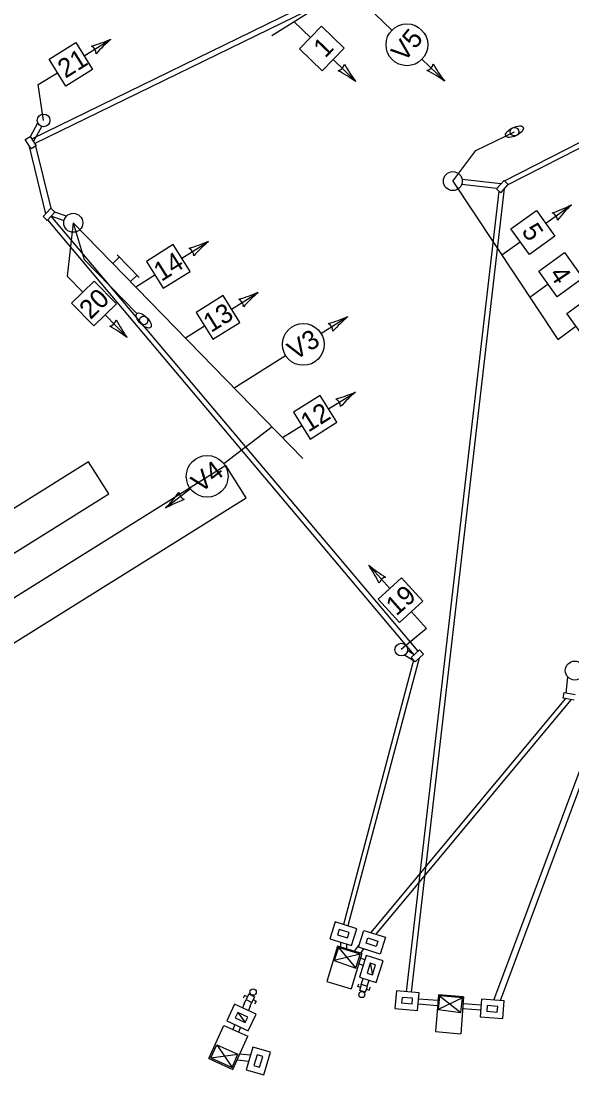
# Model space of a CAD drawing. Extents: x 981632 to 1295361, y 220574 to 1844132.
# Drawn here: x 984464.9 to 984552, y 1843245.1 to 1843411.6 of the extents above; entities that cross this region are included whole.
import ezdxf

# ---------------------------------------------------------------- set-up
doc = ezdxf.new("R2010")
doc.units = 0
for name, color, linetype in [('5', 7, 'Continuous'), ('R_Existing Luminaire', 7, 'Continuous'), ('R_Existing Signal', 7, 'Continuous'), ('R_Existing Signal Heads', 7, 'Continuous'), ('R_Existing Signal Mast Arm', 7, 'Continuous'), ('V-SIGNAL-CONDUIT', 7, 'Continuous'), ('V-SIGNAL-CONTROLLER', 7, 'Continuous'), ('V-SIGNAL-HEAD', 7, 'Continuous'), ('V-SIGNAL-MAST', 7, 'Continuous')]:
    doc.layers.add(name, color=color, linetype=linetype)

msp = doc.modelspace()

# ---------------------------------------------------------------- linework, layer by layer
at = {"layer": '5'}
for p, q in [((984548.62, 1843436.87), (984504.52, 1843409.32)), ((984473.16, 1843379.77), (984509.46, 1843342.53))]:
    msp.add_line(p, q, dxfattribs=at)
at = {"layer": 'R_Existing Luminaire'}
for p, q in [((984536.76, 1843391.22), (984542.88, 1843394.16)), ((984533.14, 1843386.36), (984536.76, 1843391.22))]:
    msp.add_line(p, q, dxfattribs=at)
msp.add_circle((984542.88, 1843394.17), 0.679, dxfattribs=at)
msp.add_ellipse((984542.88, 1843394.17), major_axis=(1.39, 0.67), ratio=0.441176, dxfattribs=at)
at = {"layer": 'R_Existing Signal'}
for p, q in [((984541.29, 1843386.39), (984590.61, 1843411.62)), ((984541.9, 1843385.8), (984591.25, 1843411.05)), ((984540.75, 1843385.92), (984534.62, 1843386.61)), ((984541.24, 1843386.43), (984540.04, 1843385.16)), ((984541.9, 1843385.8), (984541.24, 1843386.43)), ((984525.82, 1843258.27), (984540.47, 1843384.75)), ((984526.61, 1843258.2), (984541.33, 1843385.2)), ((984540.06, 1843385.19), (984534.54, 1843385.82)), ((984540.04, 1843385.16), (984540.7, 1843384.53)), ((984540.7, 1843384.53), (984541.9, 1843385.8)), ((984539.64, 1843256.94), (984571.61, 1843342.55)), ((984540.69, 1843256.86), (984572.24, 1843341.88)), ((984524.24, 1843258.4), (984524, 1843255.62)), ((984527.81, 1843258.1), (984524.24, 1843258.4)), ((984527.58, 1843255.32), (984527.81, 1843258.1)), ((984525.11, 1843257.37), (984525.04, 1843256.49)), ((984525.04, 1843256.49), (984526.71, 1843256.35)), ((984526.78, 1843257.23), (984525.11, 1843257.37)), ((984526.71, 1843256.35), (984526.78, 1843257.23)), ((984530.72, 1843256.06), (984527.66, 1843256.3)), ((984530.78, 1843256.86), (984527.73, 1843257.1)), ((984530.86, 1843257.8), (984530.39, 1843251.98)), ((984531.03, 1843257.6), (984530.84, 1843255.47)), ((984534.65, 1843257.31), (984530.84, 1843255.47)), ((984534.85, 1843257.48), (984530.86, 1843257.8)), ((984534.65, 1843257.31), (984531.03, 1843257.6)), ((984531.03, 1843257.6), (984534.43, 1843255)), ((984534.85, 1843257.48), (984534.39, 1843251.64)), ((984534.43, 1843255), (984534.65, 1843257.31)), ((984537.61, 1843256.12), (984534.76, 1843256.35)), ((984537.69, 1843257.11), (984537.46, 1843254.32)), ((984541.27, 1843256.81), (984537.69, 1843257.11)), ((984541.04, 1843254.03), (984541.27, 1843256.81)), ((984524, 1843255.62), (984527.58, 1843255.32)), ((984530.84, 1843255.47), (984534.43, 1843255)), ((984537.55, 1843255.33), (984534.7, 1843255.55)), ((984538.57, 1843256.07), (984538.5, 1843255.2)), ((984538.5, 1843255.2), (984540.16, 1843255.06)), ((984540.24, 1843255.93), (984538.57, 1843256.07)), ((984540.16, 1843255.06), (984540.24, 1843255.93)), ((984537.46, 1843254.32), (984541.04, 1843254.03)), ((984530.39, 1843251.98), (984534.39, 1843251.64))]:
    msp.add_line(p, q, dxfattribs=at)
msp.add_circle((984533.14, 1843386.36), 1.5, dxfattribs=at)
at = {"layer": 'R_Existing Signal Heads'}
for p, q in [((984547.82, 1843379.71), (984551.87, 1843382.63)), ((984540.87, 1843374.7), (984543.76, 1843376.78)), ((984545.29, 1843368.02), (984548.18, 1843370.11)), ((984549.71, 1843361.35), (984552.6, 1843363.43))]:
    msp.add_line(p, q, dxfattribs=at)
for points in [[(984545.23, 1843374.76), (984542.3, 1843378.81), (984546.36, 1843381.73), (984549.28, 1843377.68)], [(984549.65, 1843368.08), (984546.72, 1843372.14), (984550.78, 1843375.06), (984553.7, 1843371)], [(984554.07, 1843361.41), (984551.14, 1843365.46), (984555.2, 1843368.38), (984558.13, 1843364.33)]]:
    msp.add_lwpolyline(points, close=True, dxfattribs=at)
for centre, radius, start, end in [((984540.78, 1843404.24), 24.29, 289.426, 297.1642), ((984548.35, 1843380.09), 1.34, 3.9252, 67.6198), ((984568.86, 1843365.27), 24.29, 134.3808, 142.1189)]:
    msp.add_arc(centre, radius, start, end, dxfattribs=at)
at = {"layer": 'R_Existing Signal Mast Arm'}
msp.add_line((984533.14, 1843386.36), (984549.71, 1843361.35), dxfattribs=at)
msp.add_line((984533.14, 1843386.36), (984549.71, 1843361.35), dxfattribs=at)
at = {"layer": 'V-SIGNAL-CONDUIT'}
for p, q in [((984466.59, 1843393.05), (984550.6, 1843434.05)), ((984467.04, 1843392.32), (984550.02, 1843432.75)), ((984466.38, 1843393.39), (984467.56, 1843395.57)), ((984466.86, 1843392.61), (984468.17, 1843395.01)), ((984465.58, 1843392.94), (984466.36, 1843393.42)), ((984466.51, 1843391.45), (984465.58, 1843392.94)), ((984466.36, 1843393.42), (984467.28, 1843391.94)), ((984466.15, 1843392.02), (984468.78, 1843381.19)), ((984467.28, 1843391.94), (984466.51, 1843391.45)), ((984467.21, 1843391.89), (984469.59, 1843382.06)), ((984469.59, 1843382.06), (984468.39, 1843380.79)), ((984469.06, 1843380.16), (984470.26, 1843381.43)), ((984470.26, 1843381.43), (984469.59, 1843382.06)), ((984472.07, 1843380.8), (984470.26, 1843381.43)), ((984468.39, 1843380.79), (984469.06, 1843380.16)), ((984527.03, 1843311.5), (984469.14, 1843380.25)), ((984471.7, 1843380.08), (984469.66, 1843380.8)), ((984527.66, 1843312.09), (984469.66, 1843380.8)), ((984527.19, 1843310.41), (984525.49, 1843311.45)), ((984527.03, 1843311.5), (984525.99, 1843312.2)), ((984526.57, 1843311.09), (984527.86, 1843312.27)), ((984528.48, 1843311.59), (984527.19, 1843310.41)), ((984527.86, 1843312.27), (984528.48, 1843311.59)), ((984526.95, 1843310.67), (984515.85, 1843268.89)), ((984527.81, 1843310.98), (984516.56, 1843268.67)), ((984527.19, 1843310.41), (984526.57, 1843311.09)), ((984551.06, 1843305.47), (984551.29, 1843308.02)), ((984550.91, 1843304.57), (984520.19, 1843267.61)), ((984550.57, 1843304.63), (984550.72, 1843305.53)), ((984552.29, 1843304.32), (984550.57, 1843304.63)), ((984550.72, 1843305.53), (984552.45, 1843305.23)), ((984551.8, 1843304.41), (984520.99, 1843267.36)), ((984514.53, 1843269.31), (984513.69, 1843266.64)), ((984517.95, 1843268.23), (984514.53, 1843269.31)), ((984515.16, 1843268.11), (984514.89, 1843267.27)), ((984516.75, 1843267.61), (984515.16, 1843268.11)), ((984517.12, 1843265.57), (984517.95, 1843268.23)), ((984518.25, 1843265.3), (984519.09, 1843267.96)), ((984519.09, 1843267.96), (984522.51, 1843266.88)), ((984513.69, 1843266.64), (984517.12, 1843265.57)), ((984514.89, 1843267.27), (984516.49, 1843266.77)), ((984516.49, 1843266.77), (984516.75, 1843267.61)), ((984519.45, 1843265.92), (984519.71, 1843266.76)), ((984519.71, 1843266.76), (984521.31, 1843266.26)), ((984521.31, 1843266.26), (984521.05, 1843265.42)), ((984522.51, 1843266.88), (984521.67, 1843264.22)), ((984514.92, 1843265.47), (984513.23, 1843259.88)), ((984515.05, 1843265.23), (984514.41, 1843263.2)), ((984518.76, 1843264.31), (984514.92, 1843265.47)), ((984518.52, 1843264.18), (984515.05, 1843265.23)), ((984515.05, 1843265.23), (984517.81, 1843261.97)), ((984515.44, 1843265.31), (984515.43, 1843266.1)), ((984516.4, 1843265.02), (984516.39, 1843265.8)), ((984517.6, 1843264.66), (984518.39, 1843265.75)), ((984521.67, 1843264.22), (984518.25, 1843265.3)), ((984518.58, 1843264.36), (984519.07, 1843265.04)), ((984521.05, 1843265.42), (984519.45, 1843265.92)), ((984518.52, 1843264.18), (984514.41, 1843263.2)), ((984514.41, 1843263.2), (984517.81, 1843261.97)), ((984518.76, 1843264.31), (984517.06, 1843258.7)), ((984517.81, 1843261.97), (984518.52, 1843264.18)), ((984519.46, 1843263.99), (984518.38, 1843260.57)), ((984519.24, 1843263.31), (984518.54, 1843263.59)), ((984522.12, 1843263.16), (984519.46, 1843263.99)), ((984521.04, 1843259.73), (984522.12, 1843263.16)), ((984518.96, 1843262.4), (984518.26, 1843262.67)), ((984520.08, 1843262.79), (984519.58, 1843261.19)), ((984519.58, 1843261.19), (984520.42, 1843260.93)), ((984520.92, 1843262.53), (984520.08, 1843262.79)), ((984520.08, 1843262.79), (984520.42, 1843260.93)), ((984520.42, 1843260.93), (984520.92, 1843262.53)), ((984513.23, 1843259.88), (984517.06, 1843258.7)), ((984518.38, 1843260.57), (984521.04, 1843259.73)), ((984518.68, 1843259.4), (984518.99, 1843260.38)), ((984519.59, 1843259.12), (984519.9, 1843260.09)), ((984500.91, 1843257.91), (984500.47, 1843257.02)), ((984500.91, 1843257.91), (984501.81, 1843257.47)), ((984518.12, 1843259.07), (984518.26, 1843259.53)), ((984518.57, 1843258.93), (984518.12, 1843259.07)), ((984518.43, 1843258.47), (984518.71, 1843259.39)), ((984519.35, 1843258.19), (984518.43, 1843258.47)), ((984519.63, 1843259.11), (984518.71, 1843259.39)), ((984519.35, 1843258.19), (984519.63, 1843259.11)), ((984519.49, 1843258.65), (984519.95, 1843258.51)), ((984519.95, 1843258.51), (984520.09, 1843258.97)), ((984498.65, 1843256.32), (984497.42, 1843253.67)), ((984502.05, 1843254.74), (984498.65, 1843256.32)), ((984500.19, 1843256.38), (984499.92, 1843255.73)), ((984500.24, 1843257.69), (984500.02, 1843257.24)), ((984500.19, 1843256.38), (984500.47, 1843257.02)), ((984500.69, 1843257.46), (984500.24, 1843257.69)), ((984500.47, 1843257.02), (984501.37, 1843256.58)), ((984501.1, 1843255.97), (984501.38, 1843256.61)), ((984501.81, 1843257.47), (984501.37, 1843256.58)), ((984501.59, 1843257.02), (984502.04, 1843256.8)), ((984502.04, 1843256.8), (984501.82, 1843256.35)), ((984499.14, 1843254.99), (984498.75, 1843254.16)), ((984500.72, 1843254.25), (984499.14, 1843254.99)), ((984499.14, 1843254.99), (984500.34, 1843253.42)), ((984500.82, 1843252.1), (984502.05, 1843254.74)), ((984501.1, 1843255.97), (984500.83, 1843255.32)), ((984497.42, 1843253.67), (984500.82, 1843252.1)), ((984498.68, 1843253.09), (984498.36, 1843252.31)), ((984498.75, 1843254.16), (984500.34, 1843253.42)), ((984500.34, 1843253.42), (984500.72, 1843254.25)), ((984499.59, 1843252.67), (984499.27, 1843251.9)), ((984501.14, 1843248.22), (984499.48, 1843248.42)), ((984501.52, 1843249.53), (984500.48, 1843245.93)), ((984504.33, 1843248.72), (984501.52, 1843249.53)), ((984502.21, 1843248.3), (984501.72, 1843246.61)), ((984503.09, 1843248.04), (984502.21, 1843248.3)), ((984502.6, 1843246.36), (984503.09, 1843248.04)), ((984503.28, 1843245.12), (984504.33, 1843248.72)), ((984500.86, 1843247.25), (984499.16, 1843247.45)), ((984501.72, 1843246.61), (984502.6, 1843246.36)), ((984500.48, 1843245.93), (984503.28, 1843245.12))]:
    msp.add_line(p, q, dxfattribs=at)
for points in [[(984433.18, 1843315.53), (984436.36, 1843310.44), (984478.77, 1843336.93), (984475.59, 1843342.02)], [(984454.87, 1843314.93), (984458.05, 1843309.84), (984500.46, 1843336.33), (984497.28, 1843341.42)]]:
    msp.add_lwpolyline(points, close=True, dxfattribs=at)
msp.add_circle((984501.58, 1843258.21), 0.5, dxfattribs=at)
at = {"layer": 'V-SIGNAL-CONTROLLER'}
for p, q in [((984494.59, 1843247.7), (984496.94, 1843252.95)), ((984496.94, 1843252.95), (984500.75, 1843251.24)), ((984498.39, 1843245.99), (984500.75, 1843251.24)), ((984494.92, 1843247.82), (984495.84, 1843249.88)), ((984495.84, 1843249.88), (984499.19, 1843248.38)), ((984495.84, 1843249.88), (984498.27, 1843246.32)), ((984494.92, 1843247.82), (984499.19, 1843248.38)), ((984498.27, 1843246.32), (984499.19, 1843248.38)), ((984494.59, 1843247.7), (984498.39, 1843245.99)), ((984494.92, 1843247.82), (984498.27, 1843246.32))]:
    msp.add_line(p, q, dxfattribs=at)
at = {"layer": 'V-SIGNAL-HEAD'}
for p, q in [((984516.59, 1843416.86), (984523.51, 1843410.19)), ((984508.08, 1843411.54), (984510.64, 1843409.05)), ((984474.88, 1843406.14), (984479.12, 1843408.78)), ((984514.22, 1843405.56), (984517.8, 1843402.08)), ((984528.26, 1843405.61), (984531.85, 1843402.14)), ((984467.61, 1843401.61), (984470.65, 1843403.49)), ((984490.3, 1843374.2), (984494.53, 1843376.84)), ((984474.89, 1843373.97), (984483.22, 1843365.43)), ((984472.2, 1843371.35), (984474.69, 1843368.79)), ((984483.03, 1843369.65), (984486.06, 1843371.54)), ((984498.15, 1843366.13), (984502.39, 1843368.78)), ((984478.18, 1843365.21), (984481.67, 1843361.63)), ((984512.3, 1843362.3), (984516.54, 1843364.94)), ((984490.88, 1843361.59), (984493.91, 1843363.48)), ((984498.56, 1843353.71), (984506.71, 1843358.8)), ((984513.51, 1843350.38), (984517.75, 1843353.02)), ((984504.57, 1843347.55), (984496.94, 1843341.71)), ((984506.24, 1843345.83), (984509.27, 1843347.73)), ((984491.7, 1843337.71), (984487.73, 1843334.67)), ((984523.21, 1843321.98), (984519.84, 1843325.67)), ((984529, 1843315.67), (984526.59, 1843318.3)), ((984529, 1843315.67), (984524.99, 1843312.32))]:
    msp.add_line(p, q, dxfattribs=at)
for points in [[(984512.38, 1843410.84), (984508.89, 1843407.26), (984512.47, 1843403.77), (984515.96, 1843407.35)], [(984471.97, 1843401.38), (984469.33, 1843405.63), (984473.57, 1843408.27), (984476.22, 1843404.02)], [(984484.73, 1843373.67), (984487.38, 1843369.42), (984491.62, 1843372.07), (984488.97, 1843376.32)], [(984476.48, 1843370.54), (984472.9, 1843367.05), (984476.39, 1843363.47), (984479.97, 1843366.96)], [(984492.59, 1843365.6), (984495.24, 1843361.36), (984499.48, 1843364.01), (984496.83, 1843368.26)], [(984507.94, 1843349.85), (984510.59, 1843345.6), (984514.83, 1843348.25), (984512.18, 1843352.5)], [(984528.42, 1843319.99), (984524.73, 1843316.61), (984521.36, 1843320.31), (984525.05, 1843323.68)]]:
    msp.add_lwpolyline(points, close=True, dxfattribs=at)
for centre, radius in [((984525.88, 1843407.9), 3.3), ((984484.29, 1843364.33), 0.679), ((984509.51, 1843360.55), 3.3), ((984494.32, 1843339.71), 3.3)]:
    msp.add_circle(centre, radius, dxfattribs=at)
for centre, radius, start, end in [((984469.53, 1843431.1), 24.29, 285.4986, 293.2367), ((984494.88, 1843390.29), 24.29, 130.4533, 138.1915), ((984475.43, 1843406.49), 1.34, 359.9977, 63.6923), ((984514.69, 1843405.1), 1.34, 283.9193, 347.614), ((984537.16, 1843416.75), 24.29, 209.4202, 217.1583), ((984528.73, 1843405.16), 1.34, 284.1971, 347.8917), ((984551.14, 1843416.91), 24.29, 209.698, 217.4361), ((984503.65, 1843382.33), 24.29, 54.375, 62.1131), ((984517.8, 1843382.33), 24.29, 54.6527, 62.3908), ((984484.89, 1843399.14), 24.29, 285.6534, 293.3915), ((984510.35, 1843358.4), 24.29, 130.6082, 138.3463), ((984490.85, 1843374.54), 1.34, 0.1525, 63.8472), ((984492.75, 1843391.08), 24.29, 285.6534, 293.3915), ((984518.2, 1843350.34), 24.29, 130.6082, 138.3463), ((984498.71, 1843366.48), 1.34, 0.1525, 63.8472), ((984506.9, 1843387.24), 24.29, 285.6534, 293.3915), ((984532.35, 1843346.5), 24.29, 130.6082, 138.3463), ((984478.64, 1843364.74), 1.34, 282.4032, 346.0979), ((984467, 1843342.27), 24.29, 52.8589, 60.597), ((984501.41, 1843375.79), 24.29, 207.9041, 215.6422), ((984512.86, 1843362.64), 1.34, 0.1525, 63.8472), ((984508.1, 1843375.32), 24.29, 285.6534, 293.3915), ((984533.56, 1843334.58), 24.29, 130.6082, 138.3463), ((984514.07, 1843350.72), 1.34, 0.1525, 63.8472), ((984470.26, 1843351.55), 24.29, 315.9896, 323.7277), ((984491.18, 1843337.31), 1.34, 185.534, 249.2286), ((984499.42, 1843313.38), 24.29, 111.0349, 118.773), ((984535.14, 1843344.54), 24.29, 230.9722, 238.7103), ((984499.65, 1843312.17), 24.29, 26.0175, 33.7556), ((984522.77, 1843322.46), 1.34, 100.5166, 164.2112)]:
    msp.add_arc(centre, radius, start, end, dxfattribs=at)
msp.add_ellipse((984484.29, 1843364.33), major_axis=(-1.08, 1.1), ratio=0.441176, dxfattribs=at)
at = {"layer": 'V-SIGNAL-MAST'}
for p, q in [((984468.48, 1843395.96), (984467.61, 1843401.61)), ((984473.16, 1843379.77), (984472.2, 1843371.35)), ((984473.16, 1843379.77), (984474.89, 1843373.97)), ((984483.59, 1843371.15), (984480.1, 1843374.73)), ((984480.45, 1843374.38), (984479.41, 1843373.36)), ((984483.24, 1843371.51), (984482.2, 1843370.5))]:
    msp.add_line(p, q, dxfattribs=at)
for centre, radius in [((984468.48, 1843395.96), 1), ((984473.16, 1843379.77), 1.5), ((984524.99, 1843312.32), 1), ((984552.41, 1843309.02), 1.5), ((984518.76, 1843257.81), 0.478)]:
    msp.add_circle(centre, radius, dxfattribs=at)

# ---------------------------------------------------------------- texts
at = {"layer": 'R_Existing Signal Heads'}
for s, p in [('5', (984543.91, 1843378.47)), ('4', (984548.29, 1843371.67))]:
    msp.add_text(s, height=3, rotation=303.2795, dxfattribs=at).set_placement(p)
at = {"layer": 'V-SIGNAL-HEAD'}
for s, rotation, p in [('V5', 50.1993, (984525.45, 1843405.04)), ('1', 45.8538, (984512.96, 1843405.7)), ('21', 32.0021, (984471.92, 1843402.52)), ('14', 32.0021, (984487.08, 1843370.42)), ('20', 44.2069, (984475.89, 1843364.38)), ('13', 32.0021, (984494.93, 1843362.35)), ('V3', 31.9988, (984508.21, 1843357.97)), ('12', 32.0021, (984510.3, 1843346.6)), ('V4', 37.3921, (984493.27, 1843337.02)), ('19', 41.5001, (984524.21, 1843317.54))]:
    msp.add_text(s, height=3, rotation=rotation, dxfattribs=at).set_placement(p)

doc.saveas('drawing.dxf')
